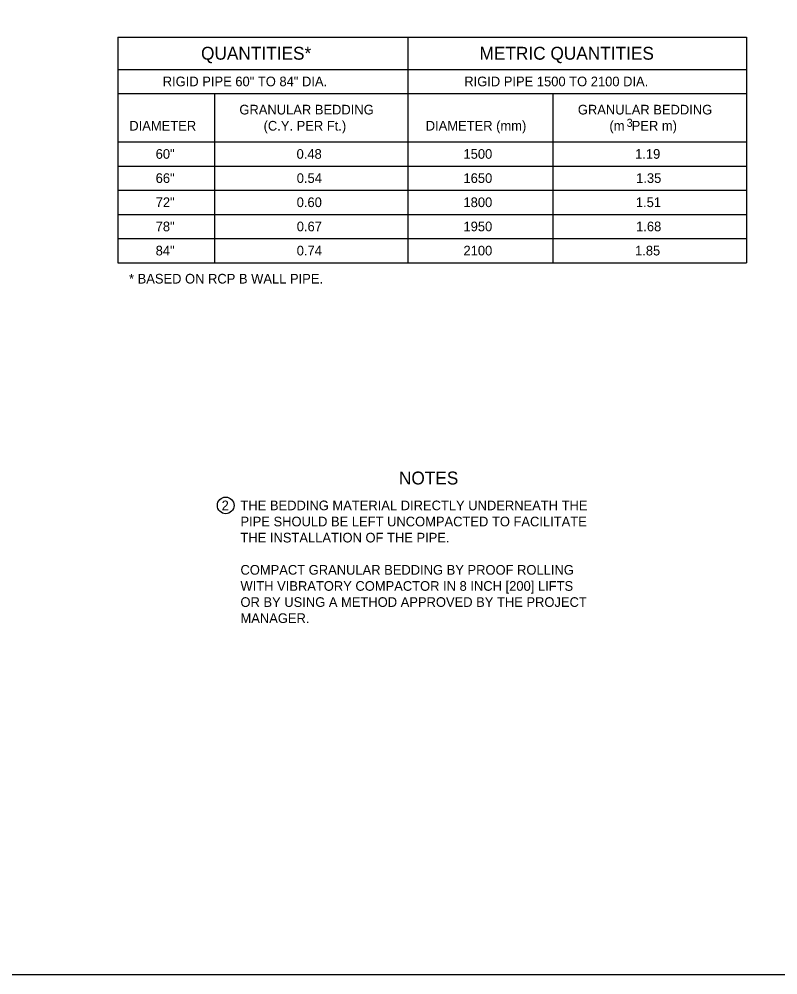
# Model space of a CAD drawing. Extents: x 49991.4 to 50061.4, y 49960.6 to 50011.4.
# Drawn here: x 50005.35 to 50010.06, y 49987.8 to 49993.73 of the extents above; entities that cross this region are included whole.
import ezdxf

# ---------------------------------------------------------------- set-up
doc = ezdxf.new("R2010")
doc.units = 0
doc.layers.add('Level 1', color=7, linetype='Continuous')
doc.layers.add('Level 2', color=7, linetype='Continuous')

msp = doc.modelspace()

# ---------------------------------------------------------------- linework, layer by layer
at = {"layer": 'Level 1'}
msp.add_lwpolyline([(49999.3835, 49998.9992), (50016.7501, 49998.9992), (50016.7501, 49987.7988), (49999.3835, 49987.7988)], close=True, dxfattribs=at)
at = {"layer": 'Level 2'}
for p, q in [((50005.9616, 49993.6201), (50005.9616, 49992.2201)), ((50005.9616, 49993.6201), (50009.8616, 49993.6201)), ((50007.7616, 49993.6201), (50007.7616, 49992.2201)), ((50009.8616, 49993.6201), (50009.8616, 49992.2201)), ((50005.9616, 49993.4201), (50009.8616, 49993.4201)), ((50005.9616, 49993.2701), (50009.8616, 49993.2701)), ((50006.5616, 49993.2701), (50006.5616, 49992.2201)), ((50008.6616, 49993.2701), (50008.6616, 49992.2201)), ((50005.9616, 49992.9701), (50009.8616, 49992.9701)), ((50005.9616, 49992.8201), (50009.8616, 49992.8201)), ((50005.9616, 49992.6701), (50009.8616, 49992.6701)), ((50005.9616, 49992.5201), (50009.8616, 49992.5201)), ((50005.9616, 49992.3701), (50009.8616, 49992.3701)), ((50005.9616, 49992.2201), (50009.8616, 49992.2201))]:
    msp.add_line(p, q, dxfattribs=at)
msp.add_circle((50006.631, 49990.7132), 0.0517, dxfattribs=at)

# ---------------------------------------------------------------- texts
for s, height, p in [('QUANTITIES*', 0.08, (50006.4782, 49993.4801)), ('METRIC QUANTITIES', 0.08, (50008.2061, 49993.4801)), ('RIGID PIPE 60" TO 84" DIA.', 0.06, (50006.2406, 49993.3151)), ('RIGID PIPE 1500 TO 2100 DIA.', 0.06, (50008.1114, 49993.3151)), ('GRANULAR BEDDING', 0.06, (50006.7161, 49993.1401)), ('GRANULAR BEDDING', 0.06, (50008.8161, 49993.1401)), ('3', 0.05, (50009.1189, 49993.0633)), ('DIAMETER', 0.06, (50006.0333, 49993.0401)), ('(C.Y. PER Ft.)', 0.06, (50006.8662, 49993.0401)), ('DIAMETER (mm)', 0.06, (50007.8724, 49993.0401)), ('(m  PER m)', 0.06, (50009.0121, 49993.0401)), ('60"', 0.06, (50006.1967, 49992.8651)), ('0.48', 0.06, (50007.0709, 49992.8651)), ('1500', 0.06, (50008.1065, 49992.8651)), ('1.19', 0.06, (50009.1714, 49992.8651)), ('66"', 0.06, (50006.1967, 49992.7151)), ('0.54', 0.06, (50007.0719, 49992.7151)), ('1650', 0.06, (50008.1065, 49992.7151)), ('1.35', 0.06, (50009.1777, 49992.7151)), ('72"', 0.06, (50006.1967, 49992.5651)), ('0.60', 0.06, (50007.0716, 49992.5651)), ('1800', 0.06, (50008.1065, 49992.5651)), ('1.51', 0.06, (50009.1761, 49992.5651)), ('78"', 0.06, (50006.1967, 49992.4151)), ('0.67', 0.06, (50007.0721, 49992.4151)), ('1950', 0.06, (50008.1065, 49992.4151)), ('1.68', 0.06, (50009.1776, 49992.4151)), ('84"', 0.06, (50006.1967, 49992.2651)), ('0.74', 0.06, (50007.0719, 49992.2651)), ('2100', 0.06, (50008.1065, 49992.2651)), ('1.85', 0.06, (50009.171, 49992.2651)), ('* BASED ON RCP B WALL PIPE.', 0.06, (50006.0312, 49992.0905)), ('NOTES', 0.08, (50007.7059, 49990.8432)), ('2', 0.06, (50006.6059, 49990.6832)), ('THE BEDDING MATERIAL DIRECTLY UNDERNEATH THE ', 0.06, (50006.7228, 49990.6832)), ('PIPE SHOULD BE LEFT UNCOMPACTED TO FACILITATE ', 0.06, (50006.7228, 49990.5832)), ('THE INSTALLATION OF THE PIPE.', 0.06, (50006.7228, 49990.4832)), ('COMPACT GRANULAR BEDDING BY PROOF ROLLING', 0.06, (50006.7228, 49990.2832)), ('WITH VIBRATORY COMPACTOR IN 8 INCH [200] LIFTS ', 0.06, (50006.7228, 49990.1832)), ('OR BY USING A METHOD APPROVED BY THE PROJECT ', 0.06, (50006.7228, 49990.0832)), ('MANAGER.', 0.06, (50006.7228, 49989.9832))]:
    msp.add_text(s, height=height, dxfattribs=at).set_placement(p)

doc.saveas('drawing.dxf')
